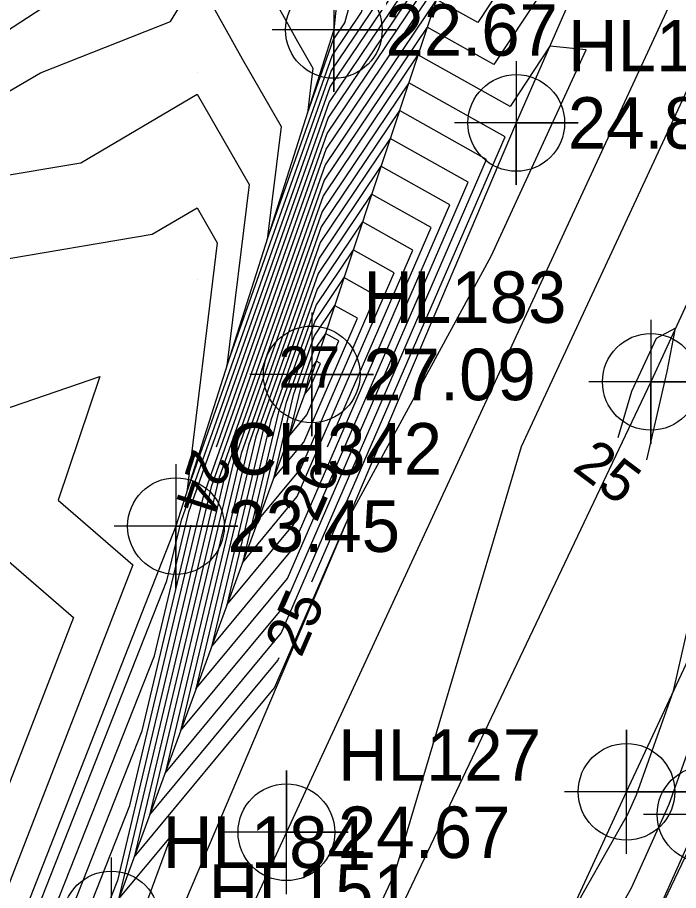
# Model space of a CAD drawing. Extents: x 2531902 to 2533249, y 715219 to 716099.
# Drawn here: x 2532801.29 to 2532833.35, y 715530.36 to 715572.69 of the extents above; entities that cross this region are included whole.
import ezdxf

# ---------------------------------------------------------------- set-up
doc = ezdxf.new("R2010")
doc.units = 0
for name, color, linetype in [('DTM Contours Major', 7, 'Continuous'), ('DTM Contours Major Text', 7, 'Continuous'), ('DTM Contours Minor', 7, 'Continuous'), ('Exist DTM Breakline', 7, 'Continuous'), ('Exist DTM Breakline Cogo Elevation', 7, 'Continuous'), ('Exist DTM Breakline Cogo Number', 7, 'Continuous'), ('Exist DTM Breakline Cogo Point CELL', 7, 'Continuous'), ('Exist DTM Crownline', 7, 'Continuous'), ('Exist DTM Crownline Cogo Point CELL', 7, 'Continuous'), ('Exist DTM Drainline', 7, 'Continuous'), ('Exist DTM QL2 LIDAR Elevation Point', 7, 'Continuous'), ('Exist Roads Soil', 7, 'Continuous'), ('Exist Roads Soil Cogo Elevation', 7, 'Continuous'), ('Exist Roads Soil Cogo Number', 7, 'Continuous'), ('Exist Roads Soil Cogo Point CELL', 7, 'Continuous')]:
    doc.layers.add(name, color=color, linetype=linetype)

msp = doc.modelspace()

# ---------------------------------------------------------------- linework, layer by layer
at = {"layer": 'DTM Contours Major'}
for points in [[(2532791.4, 715554.435), (2532792.067, 715557.933), (2532792.869, 715560), (2532794.025, 715565.975), (2532800, 715568.961), (2532800.889, 715569.111), (2532802.4, 715570), (2532808.714, 715572.49), (2532810, 715574.608), (2532812.181, 715570.686), (2532814.067, 715567.411), (2532813.398, 715561.929), (2532816.552, 715570.834), (2532817.976, 715572.954), (2532820.015, 715580.415), (2532822.987, 715583.272), (2532830.281, 715597.708), (2532833.72, 715603.995), (2532839.452, 715610.247), (2532839.495, 715610.298)], [(2532810.933, 715551.879), (2532816.309, 715567.061), (2532822.029, 715575.574)], [(2532815.569, 715545.328), (2532824.932, 715566.905), (2532820.258, 715569.526), (2532816.066, 715563.288)], [(2532816.066, 715563.288), (2532811.768, 715551.149), (2532807.69, 715534.013), (2532813.914, 715541.515), (2532813.977, 715541.659)], [(2532816.323, 715551.879), (2532820.457, 715561.405), (2532818.014, 715562.775), (2532815.823, 715559.515)], [(2532815.823, 715559.515), (2532813.576, 715553.17), (2532811.445, 715544.214), (2532814.698, 715548.135), (2532814.731, 715548.21)], [(2532832.788, 715555.52), (2532833.202, 715557.625), (2532832.262, 715557.126), (2532831.065, 715554.554), (2532830.399, 715552.308)], [(2532815.58, 715555.741), (2532815.385, 715555.191), (2532815.2, 715554.414), (2532815.483, 715554.754), (2532815.982, 715555.905), (2532815.77, 715556.024), (2532815.58, 715555.741)], [(2532831.813, 715551.24), (2532832.788, 715555.52)], [(2532770.614, 715456.33), (2532774.209, 715463.853), (2532775.265, 715467.963), (2532775.548, 715468.63), (2532782.508, 715482.632), (2532785.279, 715488.921), (2532795.075, 715509.131), (2532796.946, 715513.878), (2532802.028, 715524.659), (2532807.336, 715538.106), (2532809.708, 715548.076)]]:
    msp.add_lwpolyline(points, dxfattribs=at)
at = {"layer": 'DTM Contours Minor'}
for points in [[(2532835.464, 715590.406), (2532823.606, 715572.454), (2532821.604, 715573.577), (2532816.212, 715565.552), (2532810.683, 715549.937), (2532806.139, 715530.843), (2532805.044, 715528.068)], [(2532800, 715571.537), (2532804.65, 715574.576), (2532807.131, 715575.555), (2532809.545, 715579.531), (2532809.881, 715580), (2532805.361, 715585.361), (2532800, 715589.597)], [(2532829.193, 715527.168), (2532831.066, 715530.483), (2532832.888, 715534.551), (2532840.608, 715556.07), (2532841.778, 715561.209), (2532842.211, 715563.408), (2532842.911, 715566.611), (2532846.93, 715587.374), (2532840.977, 715584.212), (2532835.804, 715579.873), (2532834.96, 715580.492), (2532831.285, 715580.854), (2532824.389, 715570.413), (2532821.155, 715572.227), (2532816.163, 715564.797), (2532811.044, 715550.341), (2532806.188, 715529.933), (2532808.716, 715532.979), (2532806.85, 715527.886)], [(2532810.463, 715579.447), (2532814.867, 715571.53), (2532815.615, 715570.231), (2532815.35, 715568.056), (2532816.601, 715571.589), (2532817.165, 715572.43), (2532819.584, 715581.279)], [(2532800.519, 715522.955), (2532807.935, 715541.738), (2532809.597, 715548.724), (2532816.358, 715567.816), (2532821.218, 715575.05)], [(2532831.254, 715526.912), (2532834.471, 715534.097), (2532836.06, 715538.527), (2532847.289, 715561.12), (2532847.38, 715562.333), (2532848.728, 715565.06), (2532847.705, 715569.849), (2532849.505, 715575.216)], [(2532803.536, 715526.364), (2532806.738, 715534.474), (2532810.321, 715549.533), (2532816.26, 715566.306), (2532822.053, 715574.927)], [(2532799.011, 715521.251), (2532808.534, 715545.37), (2532809.236, 715548.32), (2532816.406, 715568.57), (2532820.408, 715574.526)], [(2532800, 715560.865), (2532807.823, 715562.177), (2532810, 715563.459), (2532810.972, 715561.771), (2532809.496, 715549.673), (2532816.455, 715569.325), (2532819.597, 715574.002)], [(2532800, 715564.913), (2532804.356, 715565.644), (2532810, 715568.966), (2532812.52, 715564.591), (2532811.447, 715555.801), (2532816.503, 715570.08), (2532818.787, 715573.478)], [(2532831.305, 715535.005), (2532833.109, 715540.035), (2532837.283, 715558.365), (2532838.827, 715566.205), (2532839.01, 715567.046), (2532840.066, 715572.499), (2532836.641, 715570.68), (2532833.755, 715569.147), (2532825.717, 715551.878), (2532819.573, 715531.179), (2532818.415, 715528.706), (2532817.741, 715525.005), (2532824.494, 715527.585), (2532827.83, 715528.659), (2532830.879, 715534.055), (2532831.305, 715535.005)], [(2532816.115, 715564.043), (2532811.406, 715550.745), (2532806.939, 715531.973), (2532813.758, 715540.191), (2532817.241, 715548.219), (2532824.252, 715561.113), (2532828.865, 715571.128), (2532827.107, 715571.301), (2532825.173, 715568.372), (2532820.706, 715570.877), (2532816.115, 715564.043)], [(2532816.017, 715562.533), (2532812.129, 715551.554), (2532808.441, 715536.053), (2532814.071, 715542.839), (2532824.037, 715565.805), (2532819.809, 715568.176), (2532816.017, 715562.533)], [(2532815.969, 715561.779), (2532812.491, 715551.958), (2532809.192, 715538.093), (2532814.228, 715544.163), (2532823.142, 715564.705), (2532819.36, 715566.826), (2532815.969, 715561.779)], [(2532815.92, 715561.024), (2532812.853, 715552.362), (2532809.943, 715540.134), (2532814.385, 715545.487), (2532822.247, 715563.605), (2532818.911, 715565.476), (2532815.92, 715561.024)], [(2532815.872, 715560.269), (2532813.215, 715552.766), (2532810.694, 715542.174), (2532814.542, 715546.811), (2532821.352, 715562.505), (2532818.463, 715564.126), (2532815.872, 715560.269)], [(2532815.774, 715558.76), (2532813.938, 715553.574), (2532812.196, 715546.254), (2532814.855, 715549.459), (2532819.562, 715560.305), (2532817.565, 715561.425), (2532815.774, 715558.76)], [(2532815.726, 715558.005), (2532814.3, 715553.979), (2532812.947, 715548.294), (2532815.012, 715550.783), (2532818.667, 715559.205), (2532817.116, 715560.075), (2532815.726, 715558.005)], [(2532815.677, 715557.251), (2532814.662, 715554.383), (2532813.698, 715550.334), (2532815.169, 715552.106), (2532817.772, 715558.105), (2532816.668, 715558.725), (2532815.677, 715557.251)], [(2532815.629, 715556.496), (2532815.023, 715554.787), (2532814.449, 715552.374), (2532815.326, 715553.43), (2532816.877, 715557.005), (2532816.219, 715557.375), (2532815.629, 715556.496)], [(2532783.98, 715530), (2532783.664, 715533.664), (2532786.702, 715540), (2532787.953, 715542.047), (2532790, 715543.108), (2532795.715, 715544.285), (2532798.847, 715550), (2532799.032, 715550.968), (2532800, 715553.465), (2532805.286, 715555.286), (2532803.259, 715549.282), (2532806.876, 715546.151), (2532798.435, 715524.461)], [(2532788.746, 715530), (2532788.054, 715538.054), (2532788.987, 715540), (2532789.371, 715540.629), (2532790, 715540.955), (2532797.501, 715542.499), (2532800, 715547.06), (2532804.011, 715543.588), (2532799.087, 715530.937), (2532791.086, 715528.656)]]:
    msp.add_lwpolyline(points, dxfattribs=at)
at = {"layer": 'Exist DTM Breakline'}
for points in [[(2532850.523, 715624.043), (2532846.504, 715620.874), (2532841.706, 715614.127), (2532832.845, 715598.874), (2532822.333, 715575.771), (2532815.557, 715555.383), (2532805.828, 715528.954), (2532795.014, 715502.43), (2532778.718, 715468.977), (2532762.354, 715433.263), (2532743.219, 715394.959), (2532734.198, 715371.89), (2532718.026, 715339.994), (2532703.206, 715306.913)], [(2532851.508, 715621.597), (2532844.842, 715610.805), (2532835.568, 715590.645), (2532825.478, 715567.576), (2532808.054, 715526.629), (2532792.366, 715492.682), (2532777.25, 715459.478), (2532760.672, 715423.843), (2532743.255, 715387.785), (2532725.494, 715349.638), (2532709.856, 715316.842), (2532704.172, 715304.494)], [(2532723.234, 715295.769), (2532728.306, 715306.009), (2532744.245, 715339.708), (2532761.528, 715374.58), (2532778.005, 715411.382), (2532790.122, 715438.182), (2532802.798, 715466.193), (2532818.35, 715499.828), (2532834.653, 715534.045), (2532849.974, 715564.583), (2532860.602, 715589.58), (2532870.296, 715613.283)]]:
    msp.add_lwpolyline(points, dxfattribs=at)
at = {"layer": 'Exist DTM Breakline Cogo Point CELL'}
for points in [[(2532816.632, 715575.085), (2532816.632, 715569.085), (2532816.632, 715572.085), (2532819.632, 715572.085), (2532813.632, 715572.085)], [(2532825.478, 715570.576), (2532825.478, 715564.576), (2532825.478, 715567.576), (2532828.478, 715567.576), (2532822.478, 715567.576)], [(2532815.557, 715558.383), (2532815.557, 715552.383), (2532815.557, 715555.383), (2532818.557, 715555.383), (2532812.557, 715555.383)], [(2532808.971, 715551.025), (2532808.971, 715545.025), (2532808.971, 715548.025), (2532811.971, 715548.025), (2532805.971, 715548.025)], [(2532834.653, 715537.045), (2532834.653, 715531.045), (2532834.653, 715534.045), (2532837.653, 715534.045), (2532831.653, 715534.045)], [(2532805.828, 715531.954), (2532805.828, 715525.954), (2532805.828, 715528.954), (2532808.828, 715528.954), (2532802.828, 715528.954)]]:
    msp.add_lwpolyline(points, dxfattribs=at)
for centre in [(2532816.632, 715572.085), (2532825.478, 715567.576), (2532815.557, 715555.383), (2532808.971, 715548.025), (2532834.653, 715534.045), (2532805.828, 715528.954)]:
    msp.add_circle(centre, 2.344, dxfattribs=at)
at = {"layer": 'Exist DTM Crownline'}
msp.add_lwpolyline([(2532860.933, 715617.416), (2532850.19, 715594.439), (2532832.001, 715555.022), (2532815.132, 715519.513), (2532800.101, 715487.53), (2532784.397, 715453.866), (2532768.28, 715419.409), (2532752.301, 715384.909), (2532738.247, 715354.553), (2532722.592, 715320.784), (2532713.598, 715300.468)], dxfattribs=at)
at = {"layer": 'Exist DTM Crownline Cogo Point CELL'}
msp.add_lwpolyline([(2532832.001, 715558.022), (2532832.001, 715552.022), (2532832.001, 715555.022), (2532835.001, 715555.022), (2532829.001, 715555.022)], dxfattribs=at)
msp.add_circle((2532832.001, 715555.022), 2.344, dxfattribs=at)
at = {"layer": 'Exist DTM Drainline'}
msp.add_lwpolyline([(2532840.626, 715622.249), (2532834.214, 715606.883), (2532823.996, 715594.85), (2532817.907, 715584.639), (2532816.632, 715572.085), (2532808.971, 715548.025), (2532795.108, 715512.754), (2532774.804, 715467.828), (2532771.712, 715461.016)], dxfattribs=at)
at = {"layer": 'Exist DTM QL2 LIDAR Elevation Point'}
for p, q in [((2532810, 715570), (2532810, 715570)), ((2532810, 715560), (2532810, 715560))]:
    msp.add_line(p, q, dxfattribs=at)
at = {"layer": 'Exist Roads Soil'}
for points in [[(2532854.208, 715621.565), (2532849.629, 715612.83), (2532840.293, 715590.952), (2532834.77, 715577.322), (2532814.326, 715533.181), (2532796.183, 715493.991), (2532779.839, 715458.919), (2532764.575, 715425.799), (2532746.469, 715387.058), (2532729.418, 715351.712), (2532714.481, 715319.899), (2532706.788, 715303.318)], [(2532718.476, 715296.339), (2532722.407, 715303.928), (2532737.169, 715334.721), (2532753.884, 715369.29), (2532769.727, 715403.733), (2532784.984, 715435.426), (2532799.766, 715466.715), (2532814.686, 715500.17), (2532830.822, 715535.144), (2532845.407, 715566.333), (2532858.269, 715594.216), (2532867.389, 715615.563), (2532854.208, 715621.565)]]:
    msp.add_lwpolyline(points, dxfattribs=at)
at = {"layer": 'Exist Roads Soil Cogo Point CELL'}
for points in [[(2532830.822, 715532.144), (2532830.822, 715538.144), (2532830.822, 715535.144), (2532833.822, 715535.144), (2532827.822, 715535.144)], [(2532814.326, 715530.181), (2532814.326, 715536.181), (2532814.326, 715533.181), (2532817.326, 715533.181), (2532811.326, 715533.181)]]:
    msp.add_lwpolyline(points, dxfattribs=at)
for centre in [(2532830.822, 715535.144), (2532814.326, 715533.181)]:
    msp.add_circle(centre, 2.344, dxfattribs=at)

# ---------------------------------------------------------------- texts
at = {"layer": 'DTM Contours Major Text'}
msp.add_text('27', height=2, dxfattribs=at).set_placement((2532813.95, 715554.741))
for s, rotation, p in [('25', 322.9454, (2532828.136, 715550.776)), ('24', 252.1545, (2532809.813, 715551.852)), ('26', 66.542, (2532815.796, 715548.151)), ('25', 66.542, (2532815.041, 715541.6))]:
    msp.add_text(s, height=2, rotation=rotation, dxfattribs=at).set_placement(p)
at = {"layer": 'Exist DTM Breakline Cogo Elevation'}
for s, p in [('22.67', (2532819.132, 715570.835)), ('24.88', (2532827.978, 715566.326)), ('27.09', (2532818.057, 715554.133)), ('23.45', (2532811.471, 715546.775))]:
    msp.add_text(s, height=2.5, dxfattribs=at).set_placement(p)
at = {"layer": 'Exist DTM Breakline Cogo Number'}
for s, p in [('HL150', (2532827.978, 715570.076)), ('HL183', (2532818.057, 715557.883)), ('CH342', (2532811.471, 715550.525)), ('HL184', (2532808.328, 715531.454)), ('HL151', (2532810.554, 715529.129))]:
    msp.add_text(s, height=2.5, dxfattribs=at).set_placement(p)
at = {"layer": 'Exist Roads Soil Cogo Elevation'}
msp.add_text('24.67', height=2.5, dxfattribs=at).set_placement((2532816.826, 715531.931))
at = {"layer": 'Exist Roads Soil Cogo Number'}
msp.add_text('HL127', height=2.5, dxfattribs=at).set_placement((2532816.826, 715535.681))

doc.saveas('drawing.dxf')
